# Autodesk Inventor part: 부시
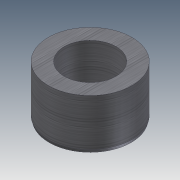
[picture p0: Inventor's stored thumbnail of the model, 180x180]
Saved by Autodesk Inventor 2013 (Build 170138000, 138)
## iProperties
Company: 한국ATC센터
Created: 2014-11
Part Number: 부시
Document SubType Name: Modeling
Designer: KYOUNG IL JANG
Density: 7.86 g/cm^3
Material: Steel, Mild
Mass: 167.601 g
Surface Area: 70.0223 cm^2
Volume: 21.3233 cm^3
Author: KYOUNG IL JANG
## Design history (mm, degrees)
sketch "스케치1"
  geometry: C1 r 21 at (0, 0); C2 r 13 at (0, 0); 1 further point
  constraints: 2 centre point, 2 coincident
  dimensions: "d4" = 26 diameter of C2; "d5" = 42 diameter of C1
extrude "돌출1" new body sketch "스케치1" distance "d0" = 25; taper "d1" = 0 deg
chamfer "모따기1" distance "d6" = 1.5; stored, may be unused: second distance "d7" = 2, angle "d8" = 15 deg
node "솔리드1"
